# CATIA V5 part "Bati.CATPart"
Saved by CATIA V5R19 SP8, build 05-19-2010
Part number: Bati
Publications: "Entraxe_bati", "Diam_ext_bati"
Bounding box of the stored display mesh (mm): x 0 to 492.616, y 0 to 319.924, z -50 to 10
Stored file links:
  F:\! CONCEPTION\PROJET\Mécanisme 590\CAO\Bati.CATPart
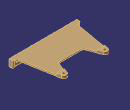
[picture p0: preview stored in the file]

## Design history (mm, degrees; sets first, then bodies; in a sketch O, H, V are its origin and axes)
Parameters
  Entraxe_bati = 300 mm
  Diam_ext_bati = 20 mm
Body1 (main body)
  Sketch1 on xy-plane, origin (0, 0, 0), H (1, 0, 0), V (0, 1, 0)
    point P1 (0, 0)
    line L1 (0, 0) -> (0, 20)
    arc A1 centre (10, 20) radius 10 from (0, 20) to (10, 30) cw
    arc A2 centre (96.3078, 300) radius 20 from (76.6117, 303.473) to (115.1017, 306.8404) cw
    point P6 (96.3078, 300)
    arc A3 centre (396.3078, 300) radius 20 from (377.514, 306.8404) to (416.004, 303.473) cw
    point P9 (396.3078, 300)
    line L2 (472.6156, 30) -> (482.6156, 30)
    arc A4 centre (482.6156, 20) radius 10 from (482.6156, 30) to (492.6156, 20) cw
    line L3 (492.6156, 20) -> (492.6156, 0)
    point P15 (492.6156, 0)
    line L4 (492.6156, 0) -> (0, 0)
    line L5 (10, 30) -> (20, 30)
    arc A5 centre (20, 40) radius 10 from (20, 30) to (29.8481, 38.2635) ccw
    line L6 (29.8481, 38.2635) -> (76.6117, 303.473)
    line L7 (115.1017, 306.8404) -> (149.1987, 213.1596)
    arc A6 centre (167.9925, 220) radius 20 from (149.1987, 213.1596) to (167.9925, 200) ccw
    line L8 (167.9925, 200) -> (324.6231, 200)
    arc A7 centre (324.6231, 220) radius 20 from (324.6231, 200) to (343.4169, 213.1596) ccw
    line L9 (343.4169, 213.1596) -> (377.514, 306.8404)
    line L10 (416.004, 303.473) -> (462.7675, 38.2635)
    arc A8 centre (472.6156, 40) radius 10 from (462.7675, 38.2635) to (472.6156, 30) ccw
    radius A2 = 20 {= Diam_ext_bati}
    radius A3 = 20 {= Diam_ext_bati}
    distance P6 P9 = 300 {= Entraxe_bati}
    radius A1 = 10
    radius A4 = 10
    radius A6 = 20
    radius A7 = 20
    length L5 = 10
    length L2 = 10
    distance L5 L4 = 30
    distance L2 L4 = 30
    angle L6 L4 = 80
    angle L10 L4 = 80
    distance P6 L4 = 300
    distance P9 L4 = 300
    radius A5 = 10
    radius A8 = 10
    distance L8 L4 = 200
    angle L7 L8 = 110
    angle L9 L8 = 110
    coincidence: P1 H, P15 H, L1 V
    vertical: L1 V, L3 V
    tangency: A1 L1, A4 L2, L3 A4, L5 A1, A5 L5, A6 L7, A7 L8, A8 L10, L6 A2, A2 L7, L9 A3, L10 A3, A8 L2, A5 L6, L8 A6, A7 L9
    horizontal: L4 H, L2 H, L8 H
  Sketch2 on yz-plane, origin (0, 0, 0), H (0, 1, 0), V (0, 0, 1)
    point P1 (0, -50)
    line L1 (0, -50) -> (20, -50)
    arc A1 centre (20, -40) radius 10 from (20, -50) to (30, -40) ccw
    line L2 (30, -40) -> (30, -20)
    arc A2 centre (40, -20) radius 10 from (30, -20) to (40, -10) cw
    line L3 (40, -10) -> (320, -10)
    line L4 (320, -10) -> (320, 10)
    point P10 (0, 0)
    line L5 (0, 0) -> (0, -50)
    line L6 (320, 10) -> (275, 10)
    line L7 (275, 10) -> (275, 0)
    point P12 (275, 0)
    line L8 (275, 0) -> (0, 0)
    point P13 (0, 0)
    radius A2 = 10
    radius A1 = 10
    distance L5 L4 = 320 {= 300mm + Diam_ext_bati}
    distance L3 H = 10
    distance L1 H = 50
    length L4 = 20
    distance L7 L4 = 45 {= Diam_ext_bati +25mm}
    distance L2 L5 = 30
    coincidence: P1 V, P10 V, P12 H, P10 O, P13 O
    horizontal: L1 H, L3 H, L8 H, L6 H
    tangency: A1 L1, L2 A1, A2 L2, L3 A2
    vertical: L4 V, L5 V, L2 V, L7 V
  SolidCombine1 "Combinaison": FirstComponentProfile Sketch1, FirstComponentDirection Sketch1, SecondComponentProfile Sketch2, SecondComponentDirection Sketch2
  Sketch3 on face of SolidCombine1 from Sketch2.L6, origin (0, 330, 10), H (0, -1, 0), V (1, 0, 0)
    circle A1 centre (30, 96.3078) radius 12.5
    point P1 (30, 96.3078)
    circle A2 centre (30, 396.3078) radius 12.5
    point P2 (30, 396.3078)
    reference projected arc E1 centre (30, 96.3078) radius 20 from (23.1596, 115.1017) to (26.527, 76.6117) ccw from edge [face of SolidCombine1 from Sketch1.A2 | face of SolidCombine1 from Sketch2.L6]
    reference projected line E2 (330, 0) -> (330, 512.9242) from edge [face of SolidCombine1 from Sketch2.L5 | face of SolidCombine1 from Sketch2.L8]
    distance P1 P2 = 300 {= Entraxe_bati}
    distance P2 E2 = 300
    radius A2 = 12.5 {= (Diam_ext_bati +5mm)/2}
    radius A1 = 12.5 {= (Diam_ext_bati +5mm)/2}
    concentricity: P1 E1
  Pocket1: profile Sketch3, direction along face of SolidCombine1 from Sketch2.L6, through (limit type 3)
